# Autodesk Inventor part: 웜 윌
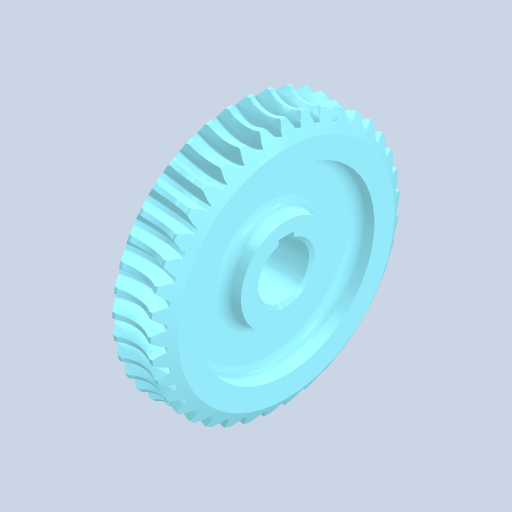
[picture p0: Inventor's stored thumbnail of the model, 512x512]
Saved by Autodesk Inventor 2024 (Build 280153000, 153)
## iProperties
Created: 2026-01
Part Number: 웜 윌
Material: 강철, 합금
Document SubType Name: Modeling
Designer: 2-10
Density: 7.73 g/cm^3
Appearance: 기본값
Author: jhkim
Sending System: Autodesk Inventor 2026
Preprocessor: ST-DEVELOPER v20.1
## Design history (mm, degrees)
feature "솔리드1"
node "솔리드2"
